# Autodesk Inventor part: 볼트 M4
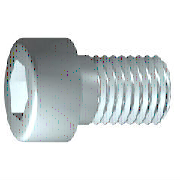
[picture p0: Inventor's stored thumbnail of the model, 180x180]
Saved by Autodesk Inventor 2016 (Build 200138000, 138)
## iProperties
IsCustomPart: 1
Created: 2015-10
Part Number: 볼트 M4
Material: 스테인리스강
Description: 6각머리 태핑 나사
Document SubType Name: Modeling
Standard: KS B 1003
Designer: mdu
Standards Organization: KS
Language: ko-KR
Size Designation: M 4 x 16
Categories: <MemberInstance><Categories><Category DisplayName="조임쇠" InternalName="e4da775c-781d-43d5-af7c-5136215cf5a6" Mnemonic="FSTN"><Category DisplayName="볼트" InternalN
Density: 8.08 g/cm^3
Mass: 2.70334 g
Surface Area: 3.81118 cm^2
Volume: 0.334572 cm^3
Appearance: 반광택
Author: mdu
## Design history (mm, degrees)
sketch "스케치1"
  geometry: L1 (-1, 0)-(16, 0); L2 (16, 0)-(16, 2); L3 (16, 2)-(1.75, 2); L4 (1.75, 2)-(1.32, 2); L5 (1.32, 2)-(0, 2); L6 (0, 2)-(0, 3.5); L7 (0, 3.5)-(-4, 3.5); L8 (-4, 3.5)-(-4, 1.732); L9 (-4, 1.732)-(-2, 1.732); L10 (-2, 1.732)-(-1, 0); L11 (-8, 0)-(20, 0) reference; L12 (0, -0.7)-(0, 4.2) reference; L13 (1.75, 2)-(0, 2)
  constraints: 22 end point, 6 parallel, 2 collinear, 2 perpendicular, 1 horizontal, 1 point on line
  dimensions: "d1" = 14.25 distance from line of L3.end L2 (= GEL); "d2" = 0.42952 distance of L4.end L3.end (computed from GAL); "d3" = 4 distance between parallel lines of L8 L6 (= KOH); "d4" = 2 distance of L8.end L9.end (= INTI); "d5" = 60 deg angle of L10 L1; "d6" = 4 diameter of L3 L1 (= GD); "d7" = 4 diameter of L5 L1 (= BDM); "d8" = 3.4641 diameter of L9 L1 (= 1.1547 x SW); "d9" = 7 diameter of L7 L1 (= KOD); "d26" = 16 distance between parallel lines of L12 L2 (= NLG)
revolve "본체" sketch "스케치1" stored, may be unused: angle "d10" = 90 deg
sketch "스케치2"
  geometry: L1 (0, -4.9)-(0, 4.9) reference; L2 (-4.9, 0)-(4.9, 0) reference; L3 (1.732, 0)-(0.866, -1.5); L4 (0.866, -1.5)-(-0.866, -1.5); L5 (-0.866, -1.5)-(-1.732, 0); L6 (-1.732, 0)-(-0.866, 1.5); L7 (-0.866, 1.5)-(0.866, 1.5); L8 (0.866, 1.5)-(1.732, 0); 2 further points
  constraints: 12 end point, 1 coincident, 1 horizontal alignment, 1 point on line, 12 other
extrude "슬롯" join sketch "스케치2" stored distance "d11" = 10; taper "d12" = 0 deg
workplane "Work Plane1"
fillet "Fillet2" dims "d30" = 0.1 (= R)
body "Solid1"
fillet "모깎기1" dims "d17" = 0.4 (= RR)
feature "스레드" dims "d13" = 14.25 (= GEL), "d14" = 0
chamfer "모따기1" distance "d15" = 0.42941 (= -0.5 x SPD + 0.5 x GD); stored, may be unused: second distance "d16" = 0.42941 (= GUL), angle "d27" = 45 deg
other parameters: "GD" = 4 (= NND) [user parameter; used in 2 equation terms], "NLG" = 16 [user parameter; used in 1 equation term], "GEL" = 14.25 [user parameter; used in 2 equation terms], "KOD" = 7 [user parameter; used in 1 equation term], "KOH" = 4 [user parameter; used in 1 equation term], "INTI" = 2 [user parameter; used in 1 equation term], "GAL" = 0.42941 (= 0.61345 x PTC) [user parameter; used in 1 equation term], "GUL" = 0.42941 (= 0.61345 x PTC) [user parameter; used in 1 equation term], "BDM" = 4 (= NND) [user parameter; used in 1 equation term], "SW" = 3 [user parameter; used in 2 equation terms], "RR" = 0.4 [user parameter; used in 1 equation term], "SPD" = 3.14117 (= NND - 1.2269 x PTC) [user parameter; used in 1 equation term], "d19" = 0, "d28" = 0, "d29" = 0, "R" = 0.1 [user parameter; used in 1 equation term], "PHH" = 0.2 [user parameter], "GD1" = 3.14117 (= THREADDIA - 1.2269 x PTC) [user parameter], "THREADDIA" = 4 [user parameter; used in 1 equation term], "FAWI" = 45 deg [user parameter], "TPU" = 14.28571 (computed from PTC) [user parameter], "PTC" = 0.7 [user parameter; used in 5 equation terms], "NND" = 4 [user parameter; used in 3 equation terms], "TOA" = 30 deg [user parameter], "E0" = 3.465 (= 1.155 x SW) [user parameter]
